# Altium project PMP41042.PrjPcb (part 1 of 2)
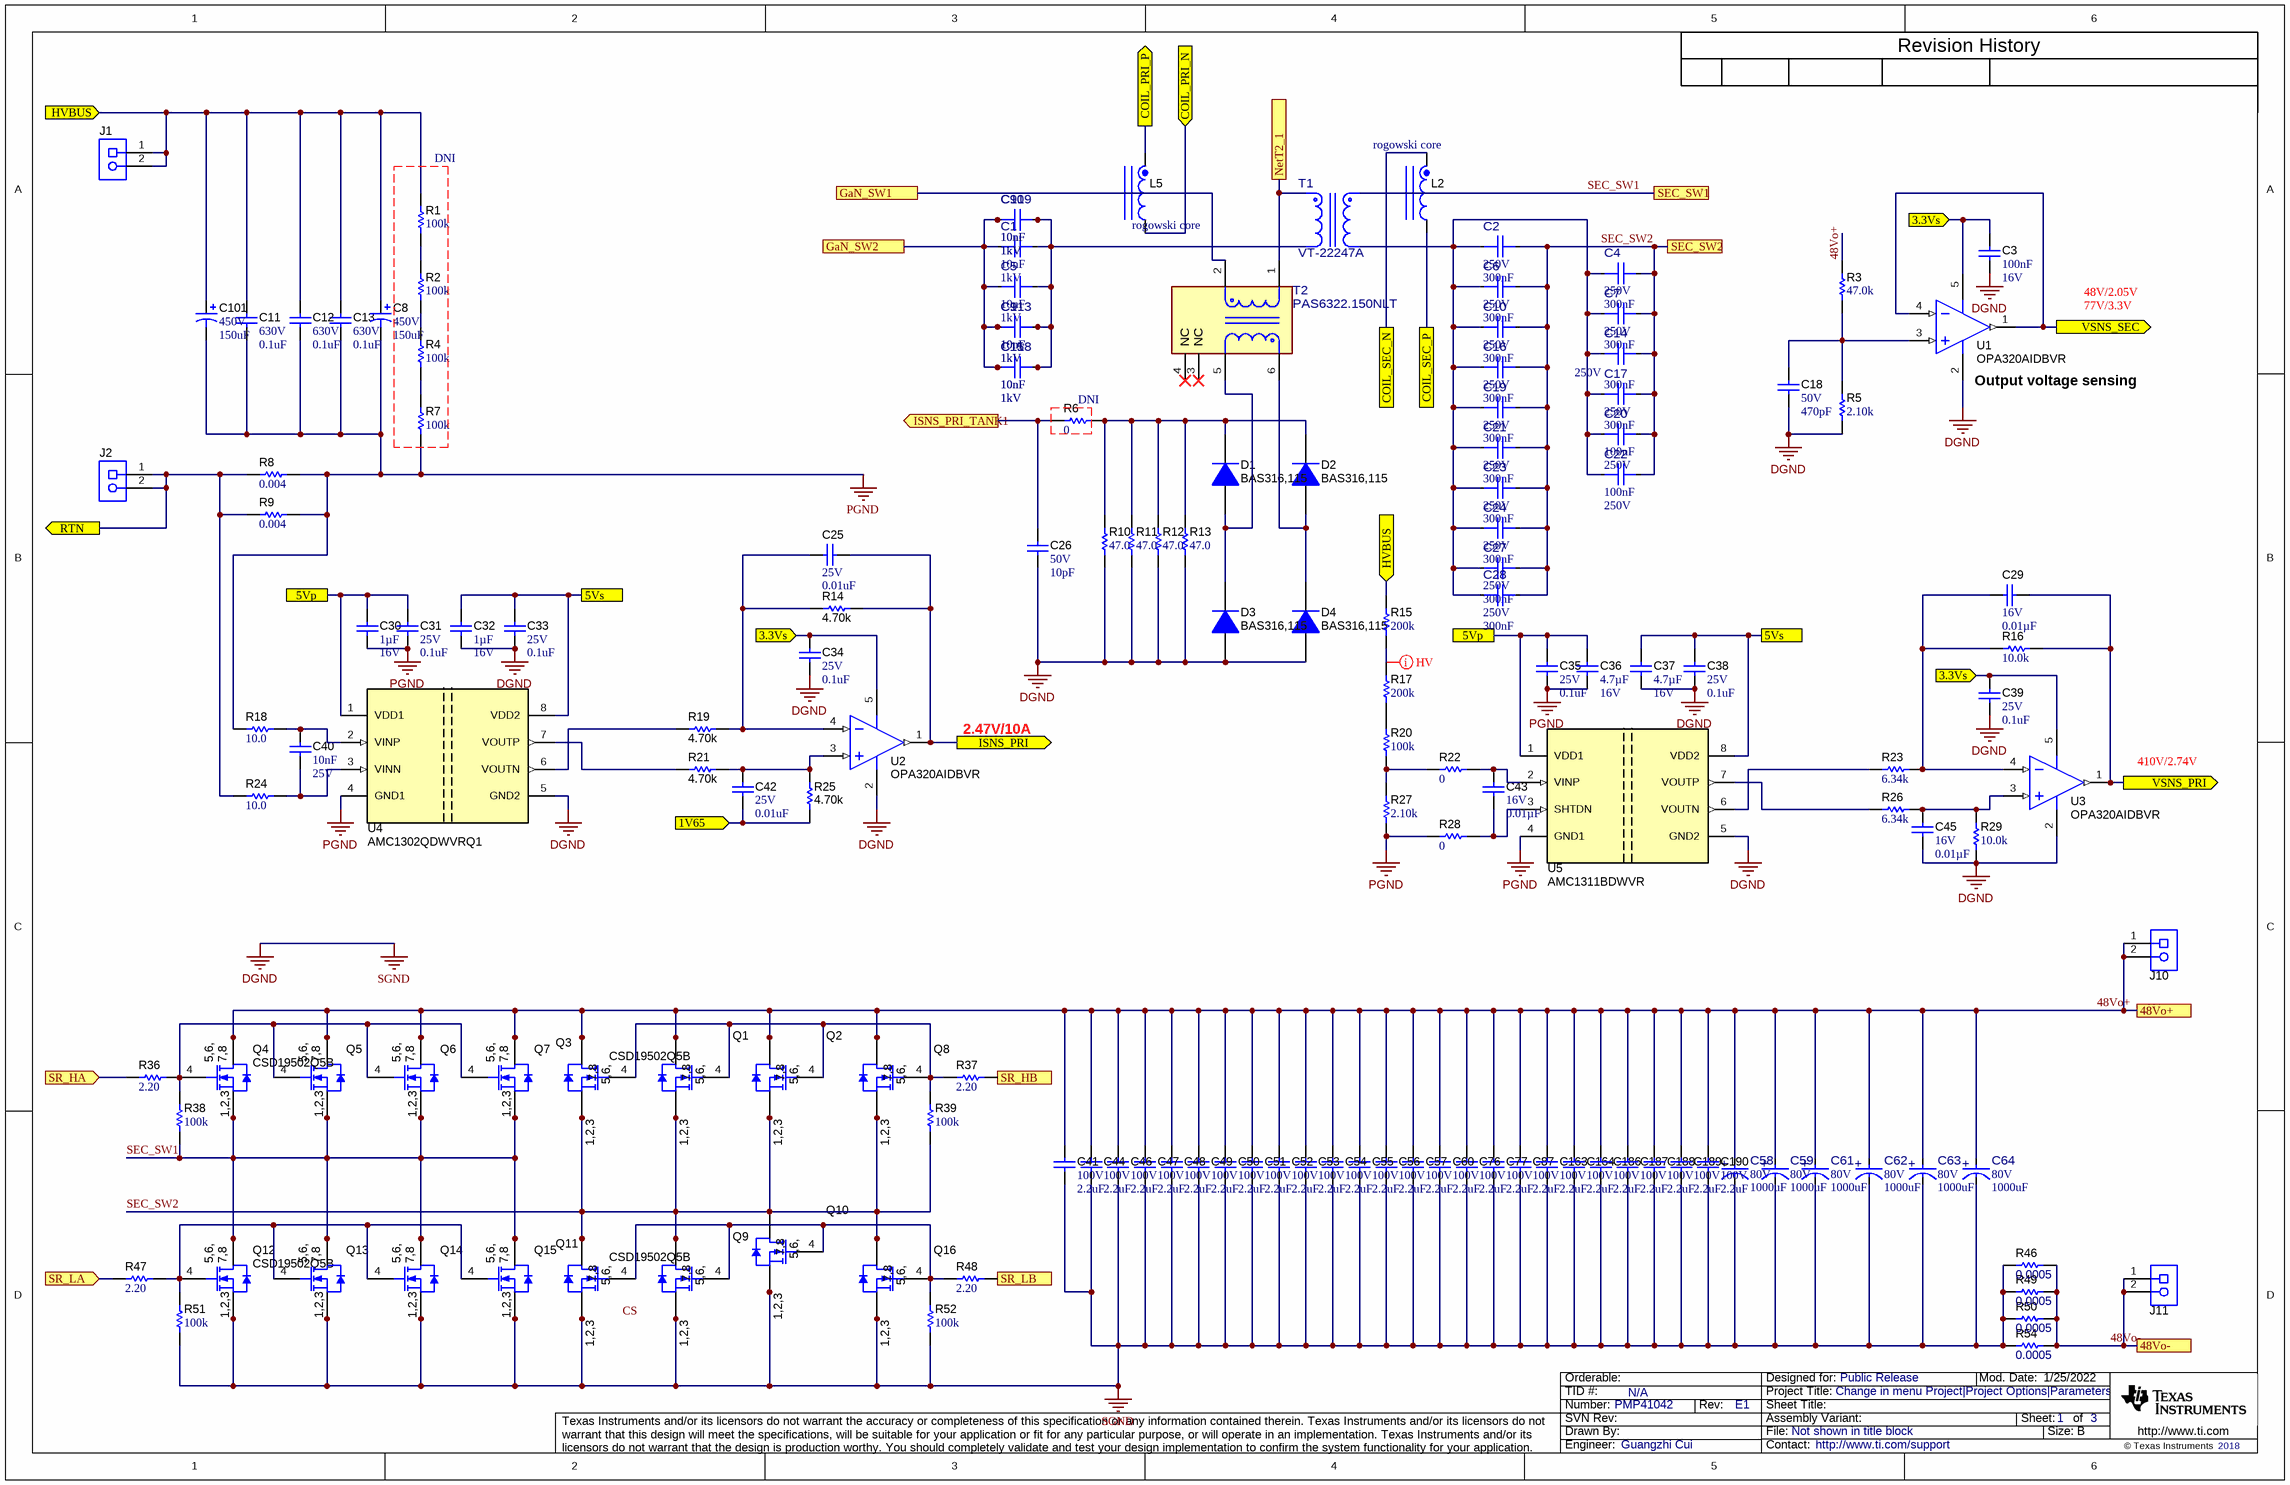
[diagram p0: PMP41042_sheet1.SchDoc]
TID: N/A; TechSupport: http://www.ti.com/support; SCH_Rev: E1; PRJ_Title: Change in menu Project|Project Options|Parameters; PRJ_Number: PMP41042; PRJ_Engineer: Guangzhi Cui; PRJ_Customer: Public Release; PCB_Rev: E1; PCB_Layout: Who did the Layout?; CopyrightYear: 2018
3 sheets, 332 parts. Net scope: flat (ports and power ports of the same name join across sheets).
Board file: PMP41042.PcbDoc
Sheets:
  PMP41042_sheet1.SchDoc
  PMP41042_sheet2.SchDoc
  BIAS.SchDoc

## Sheet PMP41042_sheet1.SchDoc
size 431 x 279 mm; Date: Not shown in title block; ApprovedBy: Not shown in title block; CheckedBy: Not shown in title block; Author: Not shown in title block; CompanyName: Not shown in title block; Engineer: Not shown in title block; Organization: Not shown in title block; Address1: Not shown in title block; Address2: Not shown in title block; Address3: Not shown in title block; Address4: Not shown in title block; DocumentNumber: 1; Revision: Use project parameter SCH_Rev; SheetNumber: 1; SheetTotal: 3; PageSetup: Record=PageOptions¦CenterHorizontal=True¦CenterVertical=True¦PrintScale=1.00¦XCorrection=1.00¦YCorrection=1.00¦PrintKind=0¦BorderSize=5000000¦LeftOffset=0¦BottomOffset=0¦Orientation=2¦PaperLength=1000¦PaperWidth=1000¦Scale=100¦PaperSource=15¦PrintQuality=600¦MediaType=1¦DitherType=10¦PaperKind=Letter¦PrintScaleMode=1

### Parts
C1  ValueDisplayed: 10nF  VDC_V: 1kV  [FP-CGA6P1C0G3A103J250AC_1210-MFG]  (hidden comment: CGA6P1C0G3A103J250AC)
C2  VDC_V: 250V  ValueDisplayed: 300nF  [FP-CKG57NC0G2E304J500JH_2220-MFG]  (hidden comment: CKG57NC0G2E304J500JH)
C3  Cap_F: 100nF  VDC_V: 16V  [0603]  (hidden comment: GRM188R71C104KA01D)
C4  VDC_V: 250V  ValueDisplayed: 300nF  [FP-CKG57NC0G2E304J500JH_2220-MFG]  (hidden comment: CKG57NC0G2E304J500JH)
C5  ValueDisplayed: 10nF  VDC_V: 1kV  [FP-CGA6P1C0G3A103J250AC_1210-MFG]  (hidden comment: CGA6P1C0G3A103J250AC)
C6  VDC_V: 250V  ValueDisplayed: 300nF  [FP-CKG57NC0G2E304J500JH_2220-MFG]  (hidden comment: CKG57NC0G2E304J500JH)
C7  VDC_V: 250V  ValueDisplayed: 300nF  [FP-CKG57NC0G2E304J500JH_2220-MFG]  (hidden comment: CKG57NC0G2E304J500JH)
C8  VDC_V: 450V  ValueDisplayed: 150uF  [BXW_1800x4500]  (hidden comment: 450BXW150MEFC18X45)
C9  ValueDisplayed: 10nF  VDC_V: 1kV  [FP-CGA6P1C0G3A103J250AC_1210-MFG]  (hidden comment: CGA6P1C0G3A103J250AC)
C10  VDC_V: 250V  ValueDisplayed: 300nF  [FP-CKG57NC0G2E304J500JH_2220-MFG]  (hidden comment: CKG57NC0G2E304J500JH)
C11  VDC_V: 630V  ValueDisplayed: 0.1uF  [1210_200]  (hidden comment: CGA6L1X7T2J104K160AC)
C12  VDC_V: 630V  ValueDisplayed: 0.1uF  [1210_200]  (hidden comment: CGA6L1X7T2J104K160AC)
C13  VDC_V: 630V  ValueDisplayed: 0.1uF  [1210_200]  (hidden comment: CGA6L1X7T2J104K160AC)
C14  VDC_V: 250V  ValueDisplayed: 300nF  [FP-CKG57NC0G2E304J500JH_2220-MFG]  (hidden comment: CKG57NC0G2E304J500JH)
C15  ValueDisplayed: 10nF  VDC_V: 1kV  [FP-CGA6P1C0G3A103J250AC_1210-MFG]  (hidden comment: CGA6P1C0G3A103J250AC)
C16  VDC_V: 250V  ValueDisplayed: 300nF  [FP-CKG57NC0G2E304J500JH_2220-MFG]  (hidden comment: CKG57NC0G2E304J500JH)
C17  VDC_V: 250V  ValueDisplayed: 300nF  [FP-CKG57NC0G2E304J500JH_2220-MFG]  (hidden comment: CKG57NC0G2E304J500JH)
C18  VDC_V: 50V  ValueDisplayed: 470pF  [0402]  (hidden comment: GRM1555C1H471JA01D)
C19  VDC_V: 250V  ValueDisplayed: 300nF  [FP-CKG57NC0G2E304J500JH_2220-MFG]  (hidden comment: CKG57NC0G2E304J500JH)
C20  ValueDisplayed: 100nF  VDC_V: 250V  [FP-C4532C0G2E104J320KN_1812-MFG]  (hidden comment: C4532C0G2E104J320KN)
C21  VDC_V: 250V  ValueDisplayed: 300nF  [FP-CKG57NC0G2E304J500JH_2220-MFG]  (hidden comment: CKG57NC0G2E304J500JH)
C22  ValueDisplayed: 100nF  VDC_V: 250V  [FP-C4532C0G2E104J320KN_1812-MFG]  (hidden comment: C4532C0G2E104J320KN)
C23  VDC_V: 250V  ValueDisplayed: 300nF  [FP-CKG57NC0G2E304J500JH_2220-MFG]  (hidden comment: CKG57NC0G2E304J500JH)
C24  VDC_V: 250V  ValueDisplayed: 300nF  [FP-CKG57NC0G2E304J500JH_2220-MFG]  (hidden comment: CKG57NC0G2E304J500JH)
C25  VDC_V: 25V  ValueDisplayed: 0.01uF  [0402]  (hidden comment: GCM155R71E103KA37D)
C26  VDC_V: 50V  ValueDisplayed: 10pF  [0402]  (hidden comment: GRM1555C1H100JA01D)
C27  VDC_V: 250V  ValueDisplayed: 300nF  [FP-CKG57NC0G2E304J500JH_2220-MFG]  (hidden comment: CKG57NC0G2E304J500JH)
C28  VDC_V: 250V  ValueDisplayed: 300nF  [FP-CKG57NC0G2E304J500JH_2220-MFG]  (hidden comment: CKG57NC0G2E304J500JH)
C29  VDC_V: 16V  ValueDisplayed: 0.01µF  [0402]  (hidden comment: CC0402KRX7R7BB103)
C30  Cap_F: 1µF  VDC_V: 16V  [0603]  (hidden comment: CGA3E1X7R1C105K080AC)
C31  VDC_V: 25V  ValueDisplayed: 0.1uF  [0402]  (hidden comment: GRM155R71E104KE14D)
C32  Cap_F: 1µF  VDC_V: 16V  [0603]  (hidden comment: CGA3E1X7R1C105K080AC)
C33  VDC_V: 25V  ValueDisplayed: 0.1uF  [0402]  (hidden comment: GRM155R71E104KE14D)
C34  VDC_V: 25V  ValueDisplayed: 0.1uF  [0402]  (hidden comment: GRM155R71E104KE14D)
C35  VDC_V: 25V  ValueDisplayed: 0.1uF  [0402]  (hidden comment: GRM155R71E104KE14D)
C36  Cap_F: 4.7µF  VDC_V: 16V  [0603]  (hidden comment: GRM188Z71C475KE21D)
C37  Cap_F: 4.7µF  VDC_V: 16V  [0603]  (hidden comment: GRM188Z71C475KE21D)
C38  VDC_V: 25V  ValueDisplayed: 0.1uF  [0402]  (hidden comment: GRM155R71E104KE14D)
C39  VDC_V: 25V  ValueDisplayed: 0.1uF  [0402]  (hidden comment: GRM155R71E104KE14D)
C40  Cap_F: 10nF  VDC_V: 25V  [0603]  (hidden comment: SR0603X7R103K1NT95(F)#M123A)
C41  VDC_V: 100V  ValueDisplayed: 2.2uF  [1206_190]  (hidden comment: GRM31CR72A225KA73L)
C42  VDC_V: 25V  ValueDisplayed: 0.01uF  [0402]  (hidden comment: GCM155R71E103KA37D)
C43  VDC_V: 16V  ValueDisplayed: 0.01µF  [0402]  (hidden comment: CC0402KRX7R7BB103)
C44  VDC_V: 100V  ValueDisplayed: 2.2uF  [1206_190]  (hidden comment: GRM31CR72A225KA73L)
C45  VDC_V: 16V  ValueDisplayed: 0.01µF  [0402]  (hidden comment: CC0402KRX7R7BB103)
C46  VDC_V: 100V  ValueDisplayed: 2.2uF  [1206_190]  (hidden comment: GRM31CR72A225KA73L)
C47  VDC_V: 100V  ValueDisplayed: 2.2uF  [1206_190]  (hidden comment: GRM31CR72A225KA73L)
C48  VDC_V: 100V  ValueDisplayed: 2.2uF  [1206_190]  (hidden comment: GRM31CR72A225KA73L)
C49  VDC_V: 100V  ValueDisplayed: 2.2uF  [1206_190]  (hidden comment: GRM31CR72A225KA73L)
C50  VDC_V: 100V  ValueDisplayed: 2.2uF  [1206_190]  (hidden comment: GRM31CR72A225KA73L)
C51  VDC_V: 100V  ValueDisplayed: 2.2uF  [1206_190]  (hidden comment: GRM31CR72A225KA73L)
C52  VDC_V: 100V  ValueDisplayed: 2.2uF  [1206_190]  (hidden comment: GRM31CR72A225KA73L)
C53  VDC_V: 100V  ValueDisplayed: 2.2uF  [1206_190]  (hidden comment: GRM31CR72A225KA73L)
C54  VDC_V: 100V  ValueDisplayed: 2.2uF  [1206_190]  (hidden comment: GRM31CR72A225KA73L)
C55  VDC_V: 100V  ValueDisplayed: 2.2uF  [1206_190]  (hidden comment: GRM31CR72A225KA73L)
C56  VDC_V: 100V  ValueDisplayed: 2.2uF  [1206_190]  (hidden comment: GRM31CR72A225KA73L)
C57  VDC_V: 100V  ValueDisplayed: 2.2uF  [1206_190]  (hidden comment: GRM31CR72A225KA73L)
C58  VDC_V: 80V  ValueDisplayed: 1000uF  [FP-EGPD800ELL102ML35H_RADIAL-MFG]  (hidden comment: EGPD800ELL102ML35H)
C59  VDC_V: 80V  ValueDisplayed: 1000uF  [FP-EGPD800ELL102ML35H_RADIAL-MFG]  (hidden comment: EGPD800ELL102ML35H)
C60  VDC_V: 100V  ValueDisplayed: 2.2uF  [1206_190]  (hidden comment: GRM31CR72A225KA73L)
C61  VDC_V: 80V  ValueDisplayed: 1000uF  [FP-EGPD800ELL102ML35H_RADIAL-MFG]  (hidden comment: EGPD800ELL102ML35H)
C62  VDC_V: 80V  ValueDisplayed: 1000uF  [FP-EGPD800ELL102ML35H_RADIAL-MFG]  (hidden comment: EGPD800ELL102ML35H)
C63  VDC_V: 80V  ValueDisplayed: 1000uF  [FP-EGPD800ELL102ML35H_RADIAL-MFG]  (hidden comment: EGPD800ELL102ML35H)
C64  VDC_V: 80V  ValueDisplayed: 1000uF  [FP-EGPD800ELL102ML35H_RADIAL-MFG]  (hidden comment: EGPD800ELL102ML35H)
C76  VDC_V: 100V  ValueDisplayed: 2.2uF  [1206_190]  (hidden comment: GRM31CR72A225KA73L)
C77  VDC_V: 100V  ValueDisplayed: 2.2uF  [1206_190]  (hidden comment: GRM31CR72A225KA73L)
C87  VDC_V: 100V  ValueDisplayed: 2.2uF  [1206_190]  (hidden comment: GRM31CR72A225KA73L)
C90  ValueDisplayed: 10nF  VDC_V: 1kV  [FP-CGA6P1C0G3A103J250AC_1210-MFG]  (hidden comment: CGA6P1C0G3A103J250AC)
C101  VDC_V: 450V  ValueDisplayed: 150uF  [BXW_1800x4500]  (hidden comment: 450BXW150MEFC18X45)
C113  ValueDisplayed: 10nF  VDC_V: 1kV  [FP-CGA6P1C0G3A103J250AC_1210-MFG]  (hidden comment: CGA6P1C0G3A103J250AC)
C118  ValueDisplayed: 10nF  VDC_V: 1kV  [FP-CGA6P1C0G3A103J250AC_1210-MFG]  (hidden comment: CGA6P1C0G3A103J250AC)
C119  ValueDisplayed: 10nF  VDC_V: 1kV  [FP-CGA6P1C0G3A103J250AC_1210-MFG]  (hidden comment: CGA6P1C0G3A183J250AC)
C163  VDC_V: 100V  ValueDisplayed: 2.2uF  [1206_190]  (hidden comment: GRM31CR72A225KA73L)
C164  VDC_V: 100V  ValueDisplayed: 2.2uF  [1206_190]  (hidden comment: GRM31CR72A225KA73L)
C186  VDC_V: 100V  ValueDisplayed: 2.2uF  [1206_190]  (hidden comment: GRM31CR72A225KA73L)
C187  VDC_V: 100V  ValueDisplayed: 2.2uF  [1206_190]  (hidden comment: GRM31CR72A225KA73L)
C188  VDC_V: 100V  ValueDisplayed: 2.2uF  [1206_190]  (hidden comment: GRM31CR72A225KA73L)
C189  VDC_V: 100V  ValueDisplayed: 2.2uF  [1206_190]  (hidden comment: GRM31CR72A225KA73L)
C190  VDC_V: 100V  ValueDisplayed: 2.2uF  [1206_190]  (hidden comment: GRM31CR72A225KA73L)
D1  BAS316,115  [SOD-323]
D2  BAS316,115  [SOD-323]
D3  BAS316,115  [SOD-323]
D4  BAS316,115  [SOD-323]
J1  282856-2  [TE_282856-2]  (value not drawn)
J2  282856-2  [TE_282856-2]  (value not drawn)
J10  282856-2  [TE_282856-2]  (value not drawn)
J11  282856-2  [TE_282856-2]  (value not drawn)
L2  RLTI-1310  [RLTI-1310]  (value not drawn)
L5  RLTI-1310  [RLTI-1310]  (value not drawn)
Q1  CSD19502Q5B  [DNK0008A]  (value not drawn)
Q2  CSD19502Q5B  [DNK0008A]  (value not drawn)
Q3  CSD19502Q5B  [DNK0008A]
Q4  CSD19502Q5B  [DNK0008A]
Q5  CSD19502Q5B  [DNK0008A]  (value not drawn)
Q6  CSD19502Q5B  [DNK0008A]  (value not drawn)
Q7  CSD19502Q5B  [DNK0008A]  (value not drawn)
Q8  CSD19502Q5B  [DNK0008A]  (value not drawn)
Q9  CSD19502Q5B  [DNK0008A]  (value not drawn)
Q10  CSD19502Q5B  [DNK0008A]  (value not drawn)
Q11  CSD19502Q5B  [DNK0008A]
Q12  CSD19502Q5B  [DNK0008A]
Q13  CSD19502Q5B  [DNK0008A]  (value not drawn)
Q14  CSD19502Q5B  [DNK0008A]  (value not drawn)
Q15  CSD19502Q5B  [DNK0008A]  (value not drawn)
Q16  CSD19502Q5B  [DNK0008A]  (value not drawn)
R1  ValueDisplayed: 100k  [1206]  (hidden comment: CRCW1206100KFKEA)
R2  ValueDisplayed: 100k  [1206]  (hidden comment: CRCW1206100KFKEA)
R3  ValueDisplayed: 47.0k  [0603]  (hidden comment: CRCW060347K0FKEA)
R4  ValueDisplayed: 100k  [1206]  (hidden comment: CRCW1206100KFKEA)
R5  ValueDisplayed: 2.10k  [0603]  (hidden comment: RC0603FR-072K1L)
R6  ValueDisplayed: 0  [0603]  (hidden comment: MCT06030Z0000ZP500)
R7  ValueDisplayed: 100k  [1206]  (hidden comment: CRCW1206100KFKEA)
R8  ValueDisplayed: 0.004  [1206]  (hidden comment: CRF1206-FZ-R004ELF)
R9  ValueDisplayed: 0.004  [1206]  (hidden comment: CRF1206-FZ-R004ELF)
R10  ValueDisplayed: 47.0  [1206]  (hidden comment: RC1206FR-0747RL)
R11  ValueDisplayed: 47.0  [1206]  (hidden comment: RC1206FR-0747RL)
R12  ValueDisplayed: 47.0  [1206]  (hidden comment: RC1206FR-0747RL)
R13  ValueDisplayed: 47.0  [1206]  (hidden comment: RC1206FR-0747RL)
R14  ValueDisplayed: 4.70k  [0402]  (hidden comment: RC0402FR-074K7L)
R15  ValueDisplayed: 200k  [1206]  (hidden comment: ERJ-8ENF2003V)
R16  ValueDisplayed: 10.0k  [0402]  (hidden comment: CRCW040210K0DHEDP)
R17  ValueDisplayed: 200k  [1206]  (hidden comment: ERJ-8ENF2003V)
R18  ValueDisplayed: 10.0  [0603]  (hidden comment: CRCW060310R0FKEA)
R19  ValueDisplayed: 4.70k  [0402]  (hidden comment: RC0402FR-074K7L)
R20  ValueDisplayed: 100k  [1206]  (hidden comment: ERJ-8ENF1003V)
R21  ValueDisplayed: 4.70k  [0402]  (hidden comment: RC0402FR-074K7L)
R22  ValueDisplayed: 0  [0603]  (hidden comment: CRCW06030000Z0EA)
R23  ValueDisplayed: 6.34k  [0402]  (hidden comment: CRCW04026K34FKED)
R24  ValueDisplayed: 10.0  [0603]  (hidden comment: CRCW060310R0FKEA)
R25  ValueDisplayed: 4.70k  [0402]  (hidden comment: RC0402FR-074K7L)
R26  ValueDisplayed: 6.34k  [0402]  (hidden comment: CRCW04026K34FKED)
R27  ValueDisplayed: 2.10k  [0603]  (hidden comment: RC0603FR-072K1L)
R28  ValueDisplayed: 0  [0603]  (hidden comment: CRCW06030000Z0EA)
R29  ValueDisplayed: 10.0k  [0402]  (hidden comment: CRCW040210K0DHEDP)
R36  ValueDisplayed: 2.20  [0603]  (hidden comment: CRCW06035R10JNEA)
R37  ValueDisplayed: 2.20  [0603]  (hidden comment: CRCW06035R10JNEA)
R38  ValueDisplayed: 100k  [0402]  (hidden comment: ERJ-2RKF1003X)
R39  ValueDisplayed: 100k  [0402]  (hidden comment: ERJ-2RKF1003X)
R46  ValueDisplayed: 0.0005  [2512]  (hidden comment: CSNL2512FTL500)
R47  ValueDisplayed: 2.20  [0603]  (hidden comment: CRCW06035R10JNEA)
R48  ValueDisplayed: 2.20  [0603]  (hidden comment: CRCW06035R10JNEA)
R49  ValueDisplayed: 0.0005  [2512]  (hidden comment: CSNL2512FTL500)
R50  ValueDisplayed: 0.0005  [2512]  (hidden comment: CSNL2512FTL500)
R51  ValueDisplayed: 100k  [0402]  (hidden comment: ERJ-2RKF1003X)
R52  ValueDisplayed: 100k  [0402]  (hidden comment: ERJ-2RKF1003X)
R54  ValueDisplayed: 0.0005  [2512]  (hidden comment: CSNL2512FTL500)
T1  VT-22247A  [FP-VT-22247A_XFRMR_70MM0_63MM0-MFG]
T2  PAS6322.150NLT  [FP-PAS6322.150NLT_SMT6_20MM5_12MM8-MFG]
U1  OPA320AIDBVR  [DBV0005A_N]
U2  OPA320AIDBVR  [DBV0005A_N]
U3  OPA320AIDBVR  [DBV0005A_N]
U4  AMC1302QDWVRQ1  [DWV0008A]
U5  AMC1311BDWVR  [DWV0008A]

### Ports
1V65 (in), 3.3Vs (in), 5Vp, 5Vs, 48Vo+, 48Vo-, COIL_PRI_N (in), COIL_PRI_P (out), COIL_SEC_N, COIL_SEC_P, GaN_SW1, GaN_SW2, HVBUS (in), ISNS_PRI (out), ISNS_PRI_TANK1 (out), NetT2_1, RTN (out), SEC_SW1, SEC_SW2, SR_HA (in), SR_HB (in), SR_LA (in), SR_LB (in), VSNS_PRI (out), VSNS_SEC (out)

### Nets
DGND: C3.2 C18.2 C26.2 C32.2 C33.2 C34.2 C37.2 C38.2 C39.2 C41.2 C44.2 C45.2 C46.2 C47.2 C48.2 C49.2 C50.2 C51.2 C52.2 C53.2 C54.2 C55.2 C56.2 C57.2 C58.1(CATHODE) C59.1(CATHODE) C60.2 C61.1(CATHODE) C62.1(CATHODE) C63.1(CATHODE) C64.1(CATHODE) C76.2 C77.2 C87.2 C163.2 C164.2 C186.2 C187.2 C188.2 C189.2 C190.2 D3.2(A) D4.2(A) Q9.1(S) Q9.2(S) Q9.3(S) Q10.1(S) Q10.2(S) Q10.3(S) Q11.1(S) Q11.2(S) Q11.3(S) Q12.1(S) Q12.2(S) Q12.3(S) Q13.1(S) Q13.2(S) Q13.3(S) Q14.1(S) Q14.2(S) Q14.3(S) Q15.1(S) Q15.2(S) Q15.3(S) Q16.1(S) Q16.2(S) Q16.3(S) R5.1 R10.1 R11.1 R12.1 R13.1 R29.1 R46.1 R49.1 R50.1 R51.1 R52.1 R54.1 U1.2(V-) U2.2(V-) U3.2(V-) U4.5(GND2) U5.5(GND2)  [also labelled SGND]
PGND: C8.2(-) C11.2 C12.2 C13.2 C30.2 C31.2 C35.2 C36.2 C101.2(-) R7.1 R8.2 R9.2 R18.1 R27.1 R28.1 U4.4(GND1) U5.4(GND1)
1V65: C42.2 R25.1 ; port 1V65
3.3Vs: C3.1 C34.1 C39.1 U1.5(V+) U2.5(V+) U3.5(V+) ; port 3.3Vs
5Vp: C30.1 C31.1 C35.1 C36.1 U4.1(VDD1) U5.1(VDD1) ; port 5Vp
5Vs: C32.1 C33.1 C37.1 C38.1 U4.8(VDD2) U5.8(VDD2) ; port 5Vs
48Vo+: C41.1 C44.1 C46.1 C47.1 C48.1 C49.1 C50.1 C51.1 C52.1 C53.1 C54.1 C55.1 C56.1 C57.1 C58.2(ANODE) C59.2(ANODE) C60.1 C61.2(ANODE) C62.2(ANODE) C63.2(ANODE) C64.2(ANODE) C76.1 C77.1 C87.1 C163.1 C164.1 C186.1 C187.1 C188.1 C189.1 C190.1 J10.1 J10.2 Q1.5(D) Q1.6(D) Q1.7(D) Q1.8(D) Q1.9(D) Q2.5(D) Q2.6(D) Q2.7(D) Q2.8(D) Q2.9(D) Q3.5(D) Q3.6(D) Q3.7(D) Q3.8(D) Q3.9(D) Q4.5(D) Q4.6(D) Q4.7(D) Q4.8(D) Q4.9(D) Q5.5(D) Q5.6(D) Q5.7(D) Q5.8(D) Q5.9(D) Q6.5(D) Q6.6(D) Q6.7(D) Q6.8(D) Q6.9(D) Q7.5(D) Q7.6(D) Q7.7(D) Q7.8(D) Q7.9(D) Q8.5(D) Q8.6(D) Q8.7(D) Q8.8(D) Q8.9(D) R3.2 ; port 48Vo+
48Vo-: J11.1 J11.2 R46.2 R49.2 R50.2 R54.2 ; port 48Vo-
COIL_PRI_N: L5.2 ; port COIL_PRI_N
COIL_PRI_P: L5.1 ; port COIL_PRI_P
COIL_SEC_N: L2.1 ; port COIL_SEC_N
COIL_SEC_P: L2.2 ; port COIL_SEC_P
GaN_SW1: T2.2 ; port GaN_SW1
GaN_SW2: C1.1 C5.1 C9.1 C15.1 C90.1 C113.1 C118.1 C119.1 ; port GaN_SW2
HVBUS: C8.1(+) C11.1 C12.1 C13.1 C101.1(+) J1.1 J1.2 R1.2 R15.2 ; port HVBUS
ISNS_PRI: C25.1 R14.2 U2.1(OUT) ; port ISNS_PRI
ISNS_PRI_TANK1: C26.1 R6.1 ; port ISNS_PRI_TANK1
NetT2_1: T2.1 ; port NetT2_1
RTN: J2.1 J2.2 R8.1 R9.1 R24.1 ; port RTN
SEC_SW1: Q4.1(S) Q4.2(S) Q4.3(S) Q5.1(S) Q5.2(S) Q5.3(S) Q6.1(S) Q6.2(S) Q6.3(S) Q7.1(S) Q7.2(S) Q7.3(S) Q12.5(D) Q12.6(D) Q12.7(D) Q12.8(D) Q12.9(D) Q13.5(D) Q13.6(D) Q13.7(D) Q13.8(D) Q13.9(D) Q14.5(D) Q14.6(D) Q14.7(D) Q14.8(D) Q14.9(D) Q15.5(D) Q15.6(D) Q15.7(D) Q15.8(D) Q15.9(D) R38.1 ; port SEC_SW1
SEC_SW2: C2.2 C4.2 C6.2 C7.2 C10.2 C14.2 C16.2 C17.2 C19.2 C20.2 C21.2 C22.2 C23.2 C24.2 C27.2 C28.2 Q1.1(S) Q1.2(S) Q1.3(S) Q2.1(S) Q2.2(S) Q2.3(S) Q3.1(S) Q3.2(S) Q3.3(S) Q8.1(S) Q8.2(S) Q8.3(S) Q9.5(D) Q9.6(D) Q9.7(D) Q9.8(D) Q9.9(D) Q10.5(D) Q10.6(D) Q10.7(D) Q10.8(D) Q10.9(D) Q11.5(D) Q11.6(D) Q11.7(D) Q11.8(D) Q11.9(D) Q16.5(D) Q16.6(D) Q16.7(D) Q16.8(D) Q16.9(D) R39.1 ; port SEC_SW2
SR_HA: R36.1 ; port SR_HA
SR_HB: R37.2 ; port SR_HB
SR_LA: R47.1 ; port SR_LA
SR_LB: R48.2 ; port SR_LB
VSNS_PRI: C29.2 R16.2 U3.1(OUT) ; port VSNS_PRI
VSNS_SEC: U1.1(OUT) U1.4(IN-) ; port VSNS_SEC
NetC1_2: C1.2 C5.2 C9.2 C15.2 C90.2 C113.2 C118.2 C119.2
NetC2_1: C2.1 C4.1 C6.1 C7.1 C10.1 C14.1 C16.1 C17.1 C19.1 C20.1 C21.1 C22.1 C23.1 C24.1 C27.1 C28.1
NetC18_1: C18.1 R3.1 R5.2 U1.3(IN+)
NetC25_2: C25.2 R14.1 R19.2 U2.4(IN-)
NetC29_1: C29.1 R16.1 R23.2 U3.4(IN-)
NetC40_1: C40.1 R18.2 U4.2(VINP)
NetC40_2: C40.2 R24.2 U4.3(VINN)
NetC42_1: C42.1 R21.2 R25.2 U2.3(IN+)
NetC43_1: C43.1 R22.2 U5.2(VINP)
NetC43_2: C43.2 R28.2 U5.3(SHTDN)
NetC45_1: C45.1 R26.2 R29.2 U3.3(IN+)
NetD1_1: D1.1(K) D2.1(K) R6.2 R10.2 R11.2 R12.2 R13.2
NetD1_2: D1.2(A) D3.1(K) T2.5
NetD2_2: D2.2(A) D4.1(K) T2.6
NetQ1_4: Q1.4(G) Q2.4(G) Q3.4(G) Q8.4(G) R37.1 R39.2
NetQ4_4: Q4.4(G) Q5.4(G) Q6.4(G) Q7.4(G) R36.2 R38.2
NetQ9_4: Q9.4(G) Q10.4(G) Q11.4(G) Q16.4(G) R48.1 R52.2
NetQ12_4: Q12.4(G) Q13.4(G) Q14.4(G) Q15.4(G) R47.2 R51.2
NetR1_1: R1.1 R2.2
NetR2_1: R2.1 R4.2
NetR4_1: R4.1 R7.2
NetR15_1: R15.1 R17.2
NetR17_1: R17.1 R20.2
NetR19_1: R19.1 U4.6(VOUTN)
NetR20_1: R20.1 R22.1 R27.2
NetR21_1: R21.1 U4.7(VOUTP)
NetR23_1: R23.1 U5.6(VOUTN)
NetR26_1: R26.1 U5.7(VOUTP)

Not connected (* = marked no-connect by the designer): T2 3(NC)* 4(NC)*

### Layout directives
net class MV: NetR15_1

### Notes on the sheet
- Revision History
- (near R1) DNI
- (near L2) rogowski core
- (near L5) rogowski core
- 48V/2.05V
- 77V/3.3V
- (near R6) DNI
- (near U1) Output voltage sensing
- 2.47V/10A
- 410V/2.74V
- Labels drawn without touching a wire or pin: CS

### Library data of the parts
C1 C5 C9 C15 C90 C113 C118 = CMP-0034099-1: Cap Ceramic 10nF 1000V C0G 5% Pad SMD 1210 +125°C Automotive T/R; Manufacturer: TDK; AEC Grade: Grade 1; AEC Qualified: Yes; SizeZ_mm: 2.8mm; TempCo: 30ppm/°C; Tolerance_%: 0.05%
C2 C4 C6 C7 C10 C14 C16 C17 C19 C21 C23 C24 C27 C28 = CMP-0097370-1: 0.3 µF ±5% 250V Ceramic Capacitor C0G, NP0 Stacked SMD, 2 J-Lead; Manufacturer: TDK; AEC Qualified: No; TempCo: 30ppm/°C; Value: 300nF; SizeZ_mm: 5.5mm
C3 = CMP-0007378-5: CAP, CERM, 0.1 uF, 16 V, +/- 10%, X7R, 0603; Manufacturer: MuRata; TaMin_C: -55°C; Polarized: N; SizeAreaWB_mm2: 4.68; Value1: Unknown; U/M: EA; Value: 0.1uF; TaMax_C: 125°C; SizeZ_mm: 1; SizeX_mm: 1.6; SizeY_mm: 0.8; SizeArea_mm2: 1.28; AEC Category: Q200
C8 C101 = CMP-0009975-3: CAP, AL, 150 uF, 450 V, +/- 20%, TH; Manufacturer: Rubycon; TaMax_C: 105°C; Value1: Unknown; SizeX_mm: 18; TaMin_C: -40°C; CompType: Capacitor; SizeZ_mm: 47; AEC Qualified: N; Value: 150uF; SizeArea_mm2: 324; AEC Category: Q200; SizeAreaWB_mm2: 400; U/M: EA; Polarized: Y; Cap_Case: 18x45mm; Cap_F: 150µF; IRMS_A: 1A
C11-C13 = CMP-0009140-2: CAP, CERM, 0.1 uF, 630 V, +/- 10%, X7R, AEC-Q200 Grade 1, 1210; Manufacturer: TDK; TaMin_C: -55°C; Polarized: N; SizeAreaWB_mm2: 14.7; Value1: Unknown; U/M: EA; Value: 0.1uF; TaMax_C: 125°C; SizeZ_mm: 2; SizeX_mm: 3.2; SizeY_mm: 2.5; Cap_Case: 1210; SizeArea_mm2: 8; AEC Qualified: Y; Cap_F: 100nF; AEC Grade: 1; AEC Category: Q200
C18 = CMP-0006470-1: CAP, CERM, 470 pF, 50 V, +/- 5%, C0G/NP0, 0402; Manufacturer: MuRata; TaMin_C: -55°C; Polarized: N; SizeAreaWB_mm2: 3; Value1: Unknown; U/M: EA; Value: 470pF; TaMax_C: 125°C; SizeZ_mm: 0.6; SizeX_mm: 1; SizeY_mm: 0.5; AEC Category: Q200
C20 C22 = CMP-0097363-1: Multilayer Ceramic Capacitors 100nF ±5% 250V C0G SMD 1812; Manufacturer: TDK; SizeZ_mm: 3.5mm; TempCo: 30ppm/°C; Tolerance_%: 0.05%; AEC Qualified: No
C25 C42 = CMP-0006352-2: CAP, CERM, 0.01 uF, 25 V, +/- 10%, X7R, 0402; Manufacturer: MuRata; TaMin_C: -55°C; Polarized: N; SizeAreaWB_mm2: 3; Value1: Unknown; U/M: EA; Value: 0.01uF; TaMax_C: 125°C; SizeZ_mm: 0.6; SizeX_mm: 1; SizeY_mm: 0.5; Cap_F: 10nF; AEC Category: Q200
C26 = CMP-0006408-1: CAP, CERM, 10 pF, 50 V, +/- 5%, C0G/NP0, 0402; Manufacturer: MuRata; TaMin_C: -55°C; Polarized: N; SizeAreaWB_mm2: 3; Value1: Unknown; U/M: EA; Value: 10pF; TaMax_C: 125°C; SizeZ_mm: 0.6; SizeX_mm: 1; SizeY_mm: 0.5; AEC Category: Q200
C29 C43 C45 = CMP-0860554-1: CAP, CERM, 0.01 µF, 16 V,+/- 10%, X7R, 0402; Manufacturer: Yageo; U/M: EA; Cap_F: 10nF; AEC Category: Q200; Value: 0.01uF; TaMax_C: 125°C; TaMin_C: -55°C; Polarized: N; SizeY_mm: 0.5; SizeAreaWB_mm2: 3; Green_REACh: Passed; SizeX_mm: 1; Green_Lifecycle: Active; SizeZ_mm: 0.6
C30 C32 = CMP-0079607-1: CAP, CERM, 1 µF, 16 V,+/- 10%, X7R, AEC-Q200 Grade 1, 0603; Manufacturer: TDK; TaMin_C: -55°C; Polarized: N; SizeAreaWB_mm2: 4.68; U/M: EA; Value: 1uF; TaMax_C: 125°C; SizeZ_mm: 1; SizeX_mm: 1.6; SizeY_mm: 0.8; SizeArea_mm2: 1.28; AEC Qualified: Y; AEC Category: Q200
C31 C33-C35 C38 C39 = CMP-0006659-2: CAP, CERM, 0.1 uF, 25 V, +/- 10%, X7R, 0402; Manufacturer: MuRata; TaMin_C: -55°C; Polarized: N; SizeAreaWB_mm2: 3; Value1: Unknown; U/M: EA; Value: 0.1uF; TaMax_C: 125°C; SizeZ_mm: 0.6; SizeX_mm: 1; SizeY_mm: 0.5; Cap_F: 100nF; AEC Category: Q200
C36 C37 = CMP-0064936-4: CAP, CERM, 4.7 uF, 16 V,+/- 10%, X7R, 0603; Manufacturer: MuRata; TaMin_C: -55°C; Polarized: N; SizeAreaWB_mm2: 4.68; Value1: Unknown; U/M: EA; Value: 4.7uF; TaMax_C: 125°C; SizeZ_mm: 1; SizeX_mm: 1.6; SizeY_mm: 0.8; SizeArea_mm2: 1.28; AEC Category: Q200
C40 = CMP-0079721-1: CAP, CERM, 0.01 µF, 25 V,+/- 10%, X7R, 0603; Manufacturer: Presidio Components; TaMin_C: -55°C; Polarized: N; SizeAreaWB_mm2: 4.68; U/M: EA; Value: 0.01uF; TaMax_C: 125°C; SizeZ_mm: 1; SizeX_mm: 1.6; SizeY_mm: 0.8; SizeArea_mm2: 1.28; AEC Category: Q200; ValueDisplayed: 0.01µF
C41 C44 C46-C57 C60 C76 C77 C87 C163 C164 C186-C190 = CMP-0008971-1: CAP, CERM, 2.2 uF, 100 V, +/- 10%, X7R, 1206_190; Manufacturer: MuRata; TaMin_C: -55°C; Polarized: N; SizeAreaWB_mm2: 10.92; Value1: Unknown; U/M: EA; Value: 2.2uF; TaMax_C: 125°C; SizeZ_mm: 1.9; SizeX_mm: 3.2; SizeY_mm: 1.6; Cap_Case: 1206; SizeArea_mm2: 5.12; Cap_F: 2.2µF; AEC Category: Q200
C58 C59 C61-C64 = CMP-0097417-1: 1000 µF 80 V Aluminum Electrolytic Capacitors Radial, Can 27mOhm @ 100kHz 2000 Hrs @ 135°C; Manufacturer: United Chemi-Con; AEC Grade: Grade 0; Value: 1mF; Leakage Current: 2400uA; AEC Qualified: Yes; IRMS_A: 4.59A; Tolerance_%: 20%; Dissipation Factor: 8%; Life: 2000Hours; SizeZ_mm: 36.5mm; Esr: 27m
C119 = CMP-0034099-1: Cap Ceramic 18nF 1000V C0G 5% Pad SMD 1210 +125°C Automotive T/R; Manufacturer: TDK; PartNumber: CGA6P1C0G3A103J250AC; AEC Grade: Grade 1; AEC Qualified: Yes; SizeZ_mm: 2.8mm; TempCo: 30ppm/°C; Tolerance_%: 0.05%; Value: 10nF
D1-D4 = CMP-0029006-2: Diode, Ultrafast, 100 V, 0.25 A, SOD-323; Manufacturer: Nexperia; SizeY_mm: 1.35; Value1: 0.25A; SizeAreaWB_mm2: 8.695; SizeZ_mm: 1; Io_A: 250mA; Value2: 1.4V; SizeX_mm: 2.7; Green_REACh: Incomplete; TJmax_C: 150°C; Green_Lifecycle: Not Set; Vr_V: 100V; AEC Category: Q101; Value: 100V; SizeArea_mm2: 3.645
J1 J2 J10 J11 = CMP-0054978-1: Therminal Block, 5 mm, 2-pole, Tin, TH; Manufacturer: TE Connectivity; CT: TRUE; CompType: Terminal Block; CNHeader: FALSE
L2 L5 = CMP-0086080-1: Inductor, Toroid, 7 µH, 1.155 ohm, TH; Manufacturer: Renco Electronics; SizeZ_mm: 18.669; SizeAreaWB_mm2: 135.836668; SizeX_mm: 4.572; AEC Qualified: N; AEC Category: Q200; Ind_H: 7µH; DCR_ohm: 1.155; Value: 7uH; Value2: A; SizeArea_mm2: 85.354668
Q1-Q16 = CMP-0000915-1: MOSFET, N-CH, 80 V, 100 A, DNK0008A (VSON-CLIP-8); Alternate Manufacturer: None; Manufacturer: Texas Instruments; SizeZ_mm: 1; ChType: N; Value2: 48 nC; VdsMax_V: 80V; SizeX_mm: 6; SizeY_mm: 5; Vgs_V: 20V; Value: 80V; SizeArea_mm2: 30; AEC Category: Q101; IdsMax_A: 100A; SizeAreaWB_mm2: 56; U/M: EA; QgTyp_nC: 48
R1 R2 R4 R7 = CMP-0016568-2: RES, 100 k, 1%, 0.25 W, 1206; Manufacturer: Vishay-Dale; Power_W: 250mW; TempCo: 100 ppm/C; U/M: EA; Value: 100k; EIA_Code: E96; SizeX_mm: 3.2; SizeY_mm: 1.6; SizeZ_mm: 1.35; Value2: 0.25W; SizeArea_mm2: 5.12; VDC_V: 200V; AEC Category: Q200
R3 = CMP-0022438-1: RES, 47.0 k, 1%, 0.1 W, AEC-Q200 Grade 0, 0603; Manufacturer: Vishay-Dale; Power_W: 100mW; TempCo: 100 ppm/C; Value_Code: 47k0; U/M: EA; Value: 47.0k; Res_ohm: 47k; SizeX_mm: 1.6; SizeY_mm: 0.8; SizeZ_mm: 1; Value2: 0.1W; SizeArea_mm2: 1.28; AEC Qualified: Y; VDC_V: 75V; AEC Grade: 0; AEC Category: Q200
R5 R27 = CMP-0022983-5: RES, 2.10 k, 1%, 0.1 W, 0603; Manufacturer: Yageo; Power_W: 100mW; TempCo: 100 ppm/C; Value_Code: 2k10; Value: 2.10k; EIA_Code: E96; Res_ohm: 2.1k; SizeX_mm: 1.6; SizeY_mm: 0.8; SizeZ_mm: 1; Value2: 0.1W; SizeArea_mm2: 1.28; AEC Qualified: N; VDC_V: 75V; AEC Category: Q200; SizeAreaWB_mm2: 4.68
R6 = CMP-0025884-2: RES, 0, 5%, 0.125 W, 0603; Manufacturer: Vishay/Beyschlag; Power_W: 125mW; TempCo: ppm/C; Value_Code: 0000; U/M: EA; Value: 0; EIA_Code: E24; SizeX_mm: 1.6; SizeY_mm: 0.8; SizeZ_mm: 1; Value2: 0.125W; SizeArea_mm2: 1.28; AEC Qualified: N; AEC Category: Q200
R8 R9 = CMP-0078823-1: RES, 0.004, 1%, 1 W, AEC-Q200 Grade 0, 1206; Manufacturer: Bourns; Value_Code: 4L000; SizeArea_mm2: 5.12; AEC Qualified: Y; AEC Category: Q200; Res_ohm: 4m; Value: 0.004; SizeZ_mm: 1.35; TempCo: 50 ppm/C; AEC Grade: 0; SizeY_mm: 1.6; Power_W: 1W; SizeX_mm: 3.2
R10-R13 = CMP-0018320-1: RES, 47.0, 1%, 0.25 W, 1206; Manufacturer: Yageo America; Power_W: 250mW; TempCo: 100 ppm/C; Value_Code: 47R0; U/M: EA; Value: 47.0; Res_ohm: 47; SizeX_mm: 3.2; SizeY_mm: 1.6; SizeZ_mm: 1.35; Value2: 0.25W; SizeArea_mm2: 5.12; VDC_V: 200V; AEC Category: Q200
R14 R19 R21 R25 = CMP-0026739-1: RES, 4.70 k, 1%, 0.0625 W, 0402; Manufacturer: Yageo America; Power_W: 62.5mW; TempCo: 100 ppm/C; Value_Code: 4k70; U/M: EA; Value: 4.70k; Res_ohm: 4.7k; SizeX_mm: 1; SizeY_mm: 0.5; SizeZ_mm: 0.6; CompType: Resistor; AEC Qualified: N; VDC_V: 50V; AEC Category: Q200
R15 R17 = CMP-0017437-1: RES, 200 k, 1%, 0.25 W, 1206; Manufacturer: Panasonic; Power_W: 250mW; TempCo: 100 ppm/C; U/M: EA; Value: 200k; EIA_Code: E96; SizeX_mm: 3.2; SizeY_mm: 1.6; SizeZ_mm: 1.35; Value2: 0.25W; SizeArea_mm2: 5.12; VDC_V: 200V; AEC Category: Q200
R16 R29 = CMP-0026769-2: RES, 10.0 k, 0.5%, 0.063 W, AEC-Q200 Grade 0, 0402; Manufacturer: Vishay-Dale; Power_W: 63mW; TempCo: 50 ppm/C; Value_Code: 10k0; Value: 10.0k; EIA_Code: E192; Res_ohm: 10k; SizeX_mm: 1; SizeY_mm: 0.5; SizeZ_mm: 0.6; Value2: 0.063W; AEC Qualified: Y; VDC_V: 50V; AEC Category: Q200; AEC Grade: 0
R18 R24 = CMP-0022003-4: RES, 10.0, 1%, 0.1 W, AEC-Q200 Grade 0, 0603; Manufacturer: Vishay-Dale; Power_W: 100mW; TempCo: 100 ppm/C; Value_Code: 10R0; Value: 10.0; EIA_Code: E96; Res_ohm: 10; SizeX_mm: 1.6; SizeY_mm: 0.8; SizeZ_mm: 1; Value2: 0.1W; SizeArea_mm2: 1.28; AEC Qualified: Y; VDC_V: 75V; AEC Category: Q200; AEC Grade: 0
R20 = CMP-0017285-1: RES, 100 k, 1%, 0.25 W, 1206; Manufacturer: Panasonic; Power_W: 250mW; TempCo: 100 ppm/C; U/M: EA; Value: 100k; EIA_Code: E96; SizeX_mm: 3.2; SizeY_mm: 1.6; SizeZ_mm: 1.35; Value2: 0.25W; SizeArea_mm2: 5.12; VDC_V: 200V; AEC Category: Q200
R22 R28 = CMP-0025697-2: RES, 0, 5%, 0.1 W, 0603; Manufacturer: Vishay-Dale; Power_W: 100mW; TempCo: 200 ppm/C; Value_Code: 0000; U/M: EA; Value: 0; EIA_Code: E24; SizeX_mm: 1.6; SizeY_mm: 0.8; SizeZ_mm: 1; Value2: 0.1W; SizeArea_mm2: 1.28; VDC_V: 75V; AEC Category: Q200
R23 R26 = CMP-0026514-2: RES, 6.34 k, 1%, 0.063 W, AEC-Q200 Grade 0, 0402; Manufacturer: Vishay-Dale; Power_W: 63mW; TempCo: 100 ppm/C; Value_Code: 6k34; Value: 6.34k; EIA_Code: E96; SizeX_mm: 1; SizeY_mm: 0.5; SizeZ_mm: 0.6; Value2: 0.063W; AEC Qualified: Y; VDC_V: 50V; AEC Category: Q200; AEC Grade: 0
R36 R37 R47 R48 = CMP-0022711-2: RES, 2.20, 1%, 0.1 W, 0603; Manufacturer: Panasonic; PartNumber: ERJ-3RQF2R2V; Power_W: 100mW; TempCo: 200 ppm/C; Value_Code: 2R20; U/M: EA; Value: 2.20; Res_ohm: 2.2; SizeX_mm: 1.6; SizeY_mm: 0.8; SizeZ_mm: 1; Value2: 0.1W; SizeArea_mm2: 1.28; AEC Category: Q200
R38 R39 R51 R52 = CMP-0026659-1: RES, 100 k, 1%, 0.1 W, 0402; Manufacturer: Panasonic; Power_W: 100mW; TempCo: 100 ppm/C; U/M: EA; Value: 100k; EIA_Code: E96; SizeX_mm: 1; SizeY_mm: 0.5; SizeZ_mm: 0.6; Value2: 0.1W; VDC_V: 50V; AEC Category: Q200
R46 R49 R50 R54 = CMP-0015817-2: RES, 0.0005, 1%, 2 W, 2512; Manufacturer: Stackpole Electronics Inc; Power_W: 3W; TempCo: ppm/C; Value_Code: 1L000; U/M: EA; Value: 0.0005; EIA_Code: E96; Res_ohm: 1m; SizeX_mm: 6.3; SizeY_mm: 3.2; SizeZ_mm: 0.71; Value2: 2W; SizeArea_mm2: 20.16; AEC Category: Q200
T1 = CMP-0097657-1: Transformer 25:3 70x63x51mm; Manufacturer: Cyntec; SizeZ_mm: 51mm; DCR_ohm: 27m; Rsec1_ohm: 850µ; AEC Qualified: No; Ind_H: 47.4µH
T2 = CMP-0097353-1: 50 A 1:150 Current Sense Transformer 20kHz ~ 1MHz 0.5mOhm Primary, 6Ohm Secondary Max 10 mH Surface Mount; Manufacturer: Pulse; Frequency_Fixed: 50-1000kHz; DCR_ohm: 500µ; Rsec1_ohm: 6; Standoff Height: 0.2mm; SizeZ_mm: 7mm; AEC Qualified: No; Voltage_Isolation_Vrms: 3500Vrms
U1-U3 = CMP-0040888-1: Precision, 20 MHz, 0.9 pA Ib, RRIO, CMOS Operational Amplifier, 1.8 to 5.5 V, -40 to 125 degC, 5-pin SOT23 (DBV5), Green (RoHS & no Sb/Br); Manufacturer: Texas Instruments; CMRR(Min)(dB): 100; Iq per channel(Max)(mA): 1.75; IIB(Max)(pA): 0.9; Total Supply Voltage(Min)(+5V is 5, +/-5V is 10): 1.8; Sub Family: High Output Current Amplifier (>=50mA), Low Input Bias Current Amp (<=10pA), Low Noise Amp (<=10nV/rtHz), Low Offset Voltage Amplifier (<=500uV), Low Supply Voltage Amplifier (<=2.7V), Precision Amplifier; Number of Channels: 2; Total Supply Voltage(Max)(+5V is 5, +/-5V is 10): 5.5; Offset Drift(Typ)(uV/C): 1.5; Vn at 1kHz(Typ)(nV/rtHz): 8.5; Slew Rate(Typ)(V/us): 10; Vio (25C)(Max)(mV): 0.15
U4 = CMP-0080587-1: Precision Reinforced Isolated Amplifier for Current Sensing, DWV0008A (SOIC-8); Alternate Manufacturer: Texas Instruments; SizeAreaWB_mm2: 105.975; SizeZ_mm: 2.8; SizeX_mm: 11.5; SizeY_mm: 5.85; SizeArea_mm2: 67.275; CompType: IC; AEC Qualified: Y; AEC Category: Q200
U5 = CMP-0078341-1: Precision, 2-V Input, Reinforced Isolated Amplifier, DWV0008A (SOIC-8); Alternate Manufacturer: Texas Instruments; SizeAreaWB_mm2: 105.975; SizeZ_mm: 2.8; SizeX_mm: 11.5; SizeY_mm: 5.85; SizeArea_mm2: 67.275; CompType: IC; AEC Qualified: N; AEC Category: Q200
